// Mitsubishi GX Works2 project: 29.6个点动+1自锁(未完)   PLC: FX3U/FX3UC

PROGRAM MAIN
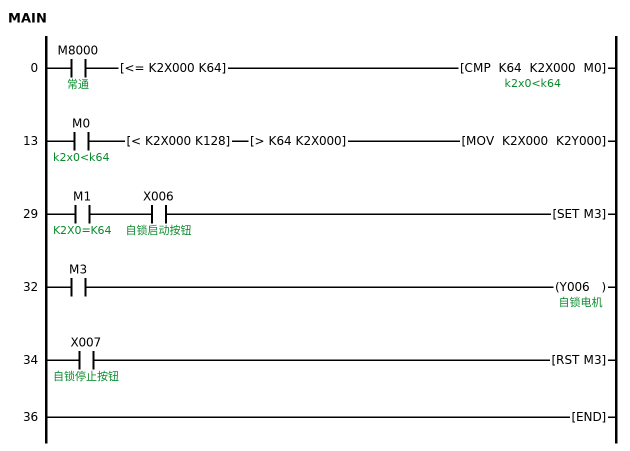
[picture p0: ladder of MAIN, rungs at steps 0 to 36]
0     LD      M8000  ; 常通
      AND<=   K2X000 K64  ; 点动按钮
      CMP     K64 K2X000 M0  ; k2x0<k64
13    LD      M0  ; k2x0<k64
      AND<    K2X000 K128  ; 点动按钮
      AND>    K64 K2X000  ; 点动按钮
      MOV     K2X000 K2Y000  ; 点动电机
29    LD      M1  ; K2X0=K64
      AND     X006  ; 自锁启动按钮
      SET     M3
32    LD      M3
      OUT     Y006  ; 自锁电机
34    LD      X007  ; 自锁停止按钮
      RST     M3
36    END
END_PROGRAM
